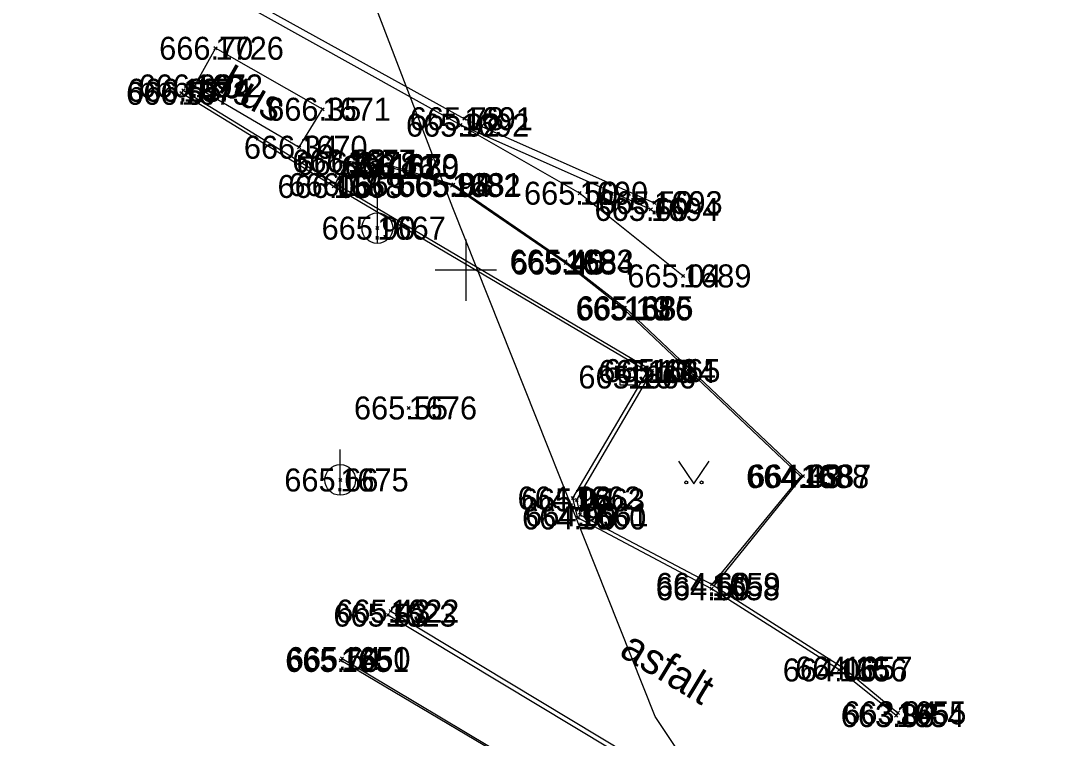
# Model space of a CAD drawing. Extents: x -844765 to -843273, y -997542 to -995529.
# Drawn here: x -844314.52 to -844280.68, y -996565.28 to -996541.86 of the extents above; entities that cross this region are included whole.
import ezdxf

# ---------------------------------------------------------------- set-up
doc = ezdxf.new("R2010")
doc.units = 0
for name, color, linetype in [('Betonový strop', 7, 'Continuous'), ('Dno', 7, 'Continuous'), ('Doplněk polohopisu', 7, 'Continuous'), ('Klenba', 7, 'Continuous'), ('Osa', 7, 'Continuous'), ('Rámeček', 7, 'Continuous'), ('Sítě podzemní nerozlišené', 7, 'Continuous'), ('Vrstva 1', 7, 'Continuous'), ('Výška', 7, 'Continuous'), ('Číslo bodu', 7, 'Continuous'), ('Řezy', 7, 'Continuous')]:
    doc.layers.add(name, color=color, linetype=linetype)

msp = doc.modelspace()

# ---------------------------------------------------------------- linework, layer by layer
at = {"layer": 'Betonový strop'}
for points in [[(-844313.39, -996537.68), (-844300.05, -996545.06), (-844293.86, -996547.8)], [(-844293.97, -996548.02), (-844300.17, -996545.27), (-844313.5, -996537.84)], [(-844309.22, -996544.13), (-844304.2, -996547.21), (-844293.93, -996553.28), (-844296.39, -996557.5), (-844296.28, -996557.99), (-844291.97, -996560.26), (-844287.67, -996562.99), (-844285.91, -996564.45)], [(-844285.97, -996564.54), (-844287.83, -996563.05), (-844291.99, -996560.4), (-844296.35, -996558.09), (-844296.51, -996557.44), (-844294.08, -996553.31), (-844304.31, -996547.27), (-844309.28, -996544.23)], [(-844300.17, -996545.27), (-844296.29, -996547.49), (-844292.92, -996550.19)], [(-844304.258, -996547.174), (-844303.86, -996546.44), (-844302.46, -996546.59), (-844300.41, -996547.21), (-844296.76, -996549.71), (-844294.81, -996551.23), (-844289.01, -996556.72), (-844291.908, -996560.299)], [(-844291.97, -996560.26), (-844289.08, -996556.74), (-844294.85, -996551.27), (-844296.75, -996549.77), (-844300.45, -996547.24), (-844302.46, -996546.65), (-844303.81, -996546.52), (-844304.2, -996547.21)], [(-844238.18, -996642.06), (-844239.24, -996647.29), (-844254.7, -996625.45), (-844265.09, -996610.79), (-844283.9, -996584.15), (-844283.04, -996578.62), (-844283.2, -996577.99), (-844284.98, -996575.45), (-844287.68, -996571.69), (-844290, -996569.21), (-844292.82, -996567.12), (-844302.54, -996561.26)], [(-844302.45, -996561.13), (-844292.72, -996567), (-844289.92, -996569.1), (-844287.58, -996571.6), (-844284.86, -996575.36), (-844283.13, -996577.92), (-844282.91, -996578.65), (-844283.74, -996584.11), (-844264.98, -996610.71), (-844254.61, -996625.37), (-844239.28, -996646.97), (-844238.31, -996642.04)], [(-844299.09, -996568.02), (-844298.56, -996566.02), (-844304.08, -996562.74)], [(-844304.04, -996562.68), (-844298.4, -996566.05), (-844298.99, -996568.07)]]:
    msp.add_lwpolyline(points, dxfattribs=at)
at = {"layer": 'Dno'}
msp.add_lwpolyline([(-844293.066, -996556.231), (-844292.566, -996556.981), (-844292.066, -996556.231)], dxfattribs=at)
for centre in [(-844292.816, -996556.931), (-844292.316, -996556.931)]:
    msp.add_circle(centre, 0.05, dxfattribs=at)
at = {"layer": 'Doplněk polohopisu'}
for p, q in [((-844302.89, -996549.13), (-844302.89, -996547.63)), ((-844294.98, -996553.49), (-844294.48, -996553.49)), ((-844304.1, -996557.35), (-844304.1, -996555.85))]:
    msp.add_line(p, q, dxfattribs=at)
msp.add_lwpolyline([(-844294.98, -996553.74), (-844294.48, -996553.74), (-844294.48, -996553.24), (-844294.98, -996553.24)], close=True, dxfattribs=at)
for centre in [(-844302.89, -996548.63), (-844304.1, -996556.85)]:
    msp.add_circle(centre, 0.5, dxfattribs=at)
at = {"layer": 'Klenba'}
for p, q in [((-844308.17, -996542.76), (-844308.85, -996543.99)), ((-844304.68, -996544.75), (-844308.17, -996542.76)), ((-844308.85, -996543.99), (-844305.44, -996545.99)), ((-844305.44, -996545.99), (-844304.68, -996544.75))]:
    msp.add_line(p, q, dxfattribs=at)
at = {"layer": 'Osa'}
msp.add_lwpolyline([(-844256.985, -996614.3), (-844264.955, -996604.805), (-844272.513, -996594.138), (-844280.435, -996583.425), (-844282.85, -996581.055), (-844288.34, -996572.812), (-844293.83, -996564.57), (-844300.425, -996547.97), (-844303.975, -996538.71), (-844307.525, -996529.45), (-844315.28, -996511.19), (-844322.67, -996492.595), (-844328.875, -996473.55)], dxfattribs=at)
at = {"layer": 'Rámeček'}
for p, q in [((-844300, -996549), (-844300, -996551)), ((-844299, -996550), (-844301, -996550))]:
    msp.add_line(p, q, dxfattribs=at)
at = {"layer": 'Sítě podzemní nerozlišené'}
for p, q in [((-844308.17, -996542.76), (-844308.22, -996542.71)), ((-844308.17, -996542.76), (-844308.22, -996542.81)), ((-844308.17, -996542.76), (-844308.12, -996542.71)), ((-844308.17, -996542.76), (-844308.12, -996542.81)), ((-844309.22, -996544.13), (-844309.27, -996544.08)), ((-844309.22, -996544.13), (-844309.27, -996544.18)), ((-844309.22, -996544.13), (-844309.17, -996544.08)), ((-844309.22, -996544.13), (-844309.17, -996544.18)), ((-844308.85, -996543.99), (-844308.9, -996543.94)), ((-844308.85, -996543.99), (-844308.9, -996544.04)), ((-844308.85, -996543.99), (-844308.8, -996543.94)), ((-844308.85, -996543.99), (-844308.8, -996544.04)), ((-844309.28, -996544.23), (-844309.33, -996544.18)), ((-844309.28, -996544.23), (-844309.33, -996544.28)), ((-844309.28, -996544.23), (-844309.23, -996544.18)), ((-844309.28, -996544.23), (-844309.23, -996544.28)), ((-844304.68, -996544.75), (-844304.73, -996544.7)), ((-844304.68, -996544.75), (-844304.73, -996544.8)), ((-844304.68, -996544.75), (-844304.63, -996544.7)), ((-844304.68, -996544.75), (-844304.63, -996544.8)), ((-844300.05, -996545.06), (-844300.1, -996545.01)), ((-844300.05, -996545.06), (-844300.1, -996545.11)), ((-844300.05, -996545.06), (-844300, -996545.01)), ((-844300.05, -996545.06), (-844300, -996545.11)), ((-844300.17, -996545.27), (-844300.22, -996545.22)), ((-844300.17, -996545.27), (-844300.22, -996545.32)), ((-844300.17, -996545.27), (-844300.12, -996545.22)), ((-844300.17, -996545.27), (-844300.12, -996545.32)), ((-844305.44, -996545.99), (-844305.49, -996545.94)), ((-844305.44, -996545.99), (-844305.49, -996546.04)), ((-844305.44, -996545.99), (-844305.39, -996545.94)), ((-844305.44, -996545.99), (-844305.39, -996546.04)), ((-844303.86, -996546.44), (-844303.91, -996546.39)), ((-844303.86, -996546.44), (-844303.91, -996546.49)), ((-844303.86, -996546.44), (-844303.81, -996546.39)), ((-844303.86, -996546.44), (-844303.81, -996546.49)), ((-844303.81, -996546.52), (-844303.86, -996546.47)), ((-844303.81, -996546.52), (-844303.76, -996546.47)), ((-844303.81, -996546.52), (-844303.86, -996546.57)), ((-844303.81, -996546.52), (-844303.76, -996546.57)), ((-844302.46, -996546.59), (-844302.51, -996546.54)), ((-844302.46, -996546.59), (-844302.51, -996546.64)), ((-844302.46, -996546.65), (-844302.51, -996546.6)), ((-844302.46, -996546.65), (-844302.51, -996546.7)), ((-844302.46, -996546.59), (-844302.41, -996546.54)), ((-844302.46, -996546.59), (-844302.41, -996546.64)), ((-844302.46, -996546.65), (-844302.41, -996546.6)), ((-844302.46, -996546.65), (-844302.41, -996546.7)), ((-844304.2, -996547.21), (-844304.25, -996547.16)), ((-844304.2, -996547.21), (-844304.15, -996547.16)), ((-844300.41, -996547.21), (-844300.46, -996547.16)), ((-844300.41, -996547.21), (-844300.36, -996547.16)), ((-844304.31, -996547.27), (-844304.36, -996547.22)), ((-844304.31, -996547.27), (-844304.36, -996547.32)), ((-844304.31, -996547.27), (-844304.26, -996547.22)), ((-844304.31, -996547.27), (-844304.26, -996547.32)), ((-844304.2, -996547.21), (-844304.25, -996547.26)), ((-844304.2, -996547.21), (-844304.15, -996547.26)), ((-844300.45, -996547.24), (-844300.5, -996547.19)), ((-844300.45, -996547.24), (-844300.5, -996547.29)), ((-844300.41, -996547.21), (-844300.46, -996547.26)), ((-844300.45, -996547.24), (-844300.4, -996547.19)), ((-844300.45, -996547.24), (-844300.4, -996547.29)), ((-844300.41, -996547.21), (-844300.36, -996547.26)), ((-844296.29, -996547.49), (-844296.34, -996547.44)), ((-844296.29, -996547.49), (-844296.34, -996547.54)), ((-844296.29, -996547.49), (-844296.24, -996547.44)), ((-844296.29, -996547.49), (-844296.24, -996547.54)), ((-844293.86, -996547.8), (-844293.91, -996547.75)), ((-844293.86, -996547.8), (-844293.91, -996547.85)), ((-844293.86, -996547.8), (-844293.81, -996547.75)), ((-844293.86, -996547.8), (-844293.81, -996547.85)), ((-844293.97, -996548.02), (-844294.02, -996547.97)), ((-844293.97, -996548.02), (-844294.02, -996548.07)), ((-844293.97, -996548.02), (-844293.92, -996547.97)), ((-844293.97, -996548.02), (-844293.92, -996548.07)), ((-844302.89, -996548.63), (-844302.94, -996548.58)), ((-844302.89, -996548.63), (-844302.94, -996548.68)), ((-844302.89, -996548.63), (-844302.84, -996548.58)), ((-844302.89, -996548.63), (-844302.84, -996548.68)), ((-844296.76, -996549.71), (-844296.81, -996549.66)), ((-844296.76, -996549.71), (-844296.81, -996549.76)), ((-844296.75, -996549.77), (-844296.8, -996549.72)), ((-844296.75, -996549.77), (-844296.8, -996549.82)), ((-844296.76, -996549.71), (-844296.71, -996549.66)), ((-844296.76, -996549.71), (-844296.71, -996549.76)), ((-844296.75, -996549.77), (-844296.7, -996549.72)), ((-844296.75, -996549.77), (-844296.7, -996549.82)), ((-844292.92, -996550.19), (-844292.97, -996550.14)), ((-844292.92, -996550.19), (-844292.97, -996550.24)), ((-844292.92, -996550.19), (-844292.87, -996550.14)), ((-844292.92, -996550.19), (-844292.87, -996550.24)), ((-844294.85, -996551.27), (-844294.9, -996551.22)), ((-844294.81, -996551.23), (-844294.86, -996551.18)), ((-844294.81, -996551.23), (-844294.86, -996551.28)), ((-844294.85, -996551.27), (-844294.8, -996551.22)), ((-844294.81, -996551.23), (-844294.76, -996551.18)), ((-844294.81, -996551.23), (-844294.76, -996551.28)), ((-844294.85, -996551.27), (-844294.9, -996551.32)), ((-844294.85, -996551.27), (-844294.8, -996551.32)), ((-844294.08, -996553.31), (-844294.13, -996553.26)), ((-844294.08, -996553.31), (-844294.03, -996553.26)), ((-844293.93, -996553.28), (-844293.98, -996553.23)), ((-844293.93, -996553.28), (-844293.88, -996553.23)), ((-844294.73, -996553.49), (-844294.78, -996553.44)), ((-844294.73, -996553.49), (-844294.78, -996553.54)), ((-844294.73, -996553.49), (-844294.68, -996553.44)), ((-844294.73, -996553.49), (-844294.68, -996553.54)), ((-844294.08, -996553.31), (-844294.13, -996553.36)), ((-844294.08, -996553.31), (-844294.03, -996553.36)), ((-844293.93, -996553.28), (-844293.98, -996553.33)), ((-844293.93, -996553.28), (-844293.88, -996553.33)), ((-844301.87, -996554.5), (-844301.92, -996554.45)), ((-844301.87, -996554.5), (-844301.92, -996554.55)), ((-844301.87, -996554.5), (-844301.82, -996554.45)), ((-844301.87, -996554.5), (-844301.82, -996554.55)), ((-844304.1, -996556.85), (-844304.15, -996556.8)), ((-844304.1, -996556.85), (-844304.15, -996556.9)), ((-844304.1, -996556.85), (-844304.05, -996556.8)), ((-844304.1, -996556.85), (-844304.05, -996556.9)), ((-844289.08, -996556.74), (-844289.13, -996556.69)), ((-844289.08, -996556.74), (-844289.13, -996556.79)), ((-844289.08, -996556.74), (-844289.03, -996556.69)), ((-844289.08, -996556.74), (-844289.03, -996556.79)), ((-844289.01, -996556.72), (-844289.06, -996556.67)), ((-844289.01, -996556.72), (-844289.06, -996556.77)), ((-844289.01, -996556.72), (-844288.96, -996556.67)), ((-844289.01, -996556.72), (-844288.96, -996556.77)), ((-844296.51, -996557.44), (-844296.56, -996557.39)), ((-844296.51, -996557.44), (-844296.56, -996557.49)), ((-844296.51, -996557.44), (-844296.46, -996557.39)), ((-844296.51, -996557.44), (-844296.46, -996557.49)), ((-844296.39, -996557.5), (-844296.44, -996557.45)), ((-844296.39, -996557.5), (-844296.44, -996557.55)), ((-844296.39, -996557.5), (-844296.34, -996557.45)), ((-844296.39, -996557.5), (-844296.34, -996557.55)), ((-844296.28, -996557.99), (-844296.33, -996557.94)), ((-844296.28, -996557.99), (-844296.33, -996558.04)), ((-844296.28, -996557.99), (-844296.23, -996557.94)), ((-844296.28, -996557.99), (-844296.23, -996558.04)), ((-844296.35, -996558.09), (-844296.4, -996558.04)), ((-844296.35, -996558.09), (-844296.4, -996558.14)), ((-844296.35, -996558.09), (-844296.3, -996558.04)), ((-844296.35, -996558.09), (-844296.3, -996558.14)), ((-844291.99, -996560.4), (-844292.04, -996560.35)), ((-844291.97, -996560.26), (-844292.02, -996560.21)), ((-844291.97, -996560.26), (-844292.02, -996560.31)), ((-844291.99, -996560.4), (-844291.94, -996560.35)), ((-844291.97, -996560.26), (-844291.92, -996560.21)), ((-844291.97, -996560.26), (-844291.92, -996560.31)), ((-844291.99, -996560.4), (-844292.04, -996560.45)), ((-844291.99, -996560.4), (-844291.94, -996560.45)), ((-844302.54, -996561.26), (-844302.59, -996561.21)), ((-844302.54, -996561.26), (-844302.59, -996561.31)), ((-844302.54, -996561.26), (-844302.49, -996561.21)), ((-844302.54, -996561.26), (-844302.49, -996561.31)), ((-844302.45, -996561.13), (-844302.5, -996561.08)), ((-844302.45, -996561.13), (-844302.5, -996561.18)), ((-844302.45, -996561.13), (-844302.4, -996561.08)), ((-844302.45, -996561.13), (-844302.4, -996561.18)), ((-844304.08, -996562.74), (-844304.13, -996562.69)), ((-844304.08, -996562.74), (-844304.13, -996562.79)), ((-844304.04, -996562.68), (-844304.09, -996562.63)), ((-844304.04, -996562.68), (-844304.09, -996562.73)), ((-844304.08, -996562.74), (-844304.03, -996562.69)), ((-844304.08, -996562.74), (-844304.03, -996562.79)), ((-844304.04, -996562.68), (-844303.99, -996562.63)), ((-844304.04, -996562.68), (-844303.99, -996562.73)), ((-844287.83, -996563.05), (-844287.88, -996563)), ((-844287.83, -996563.05), (-844287.88, -996563.1)), ((-844287.83, -996563.05), (-844287.78, -996563)), ((-844287.83, -996563.05), (-844287.78, -996563.1)), ((-844287.67, -996562.99), (-844287.72, -996562.94)), ((-844287.67, -996562.99), (-844287.72, -996563.04)), ((-844287.67, -996562.99), (-844287.62, -996562.94)), ((-844287.67, -996562.99), (-844287.62, -996563.04)), ((-844285.91, -996564.45), (-844285.96, -996564.4)), ((-844285.91, -996564.45), (-844285.86, -996564.4)), ((-844285.97, -996564.54), (-844286.02, -996564.49)), ((-844285.97, -996564.54), (-844286.02, -996564.59)), ((-844285.97, -996564.54), (-844285.92, -996564.49)), ((-844285.97, -996564.54), (-844285.92, -996564.59)), ((-844285.91, -996564.45), (-844285.96, -996564.5)), ((-844285.91, -996564.45), (-844285.86, -996564.5))]:
    msp.add_line(p, q, dxfattribs=at)

# ---------------------------------------------------------------- texts
at = {"layer": 'Vrstva 1'}
msp.add_text('bus', height=1, rotation=330.3082, dxfattribs=at).set_placement((-844308.116, -996544.152))
at = {"layer": 'Výška'}
msp.add_text('asfalt', height=1, rotation=328.8979, dxfattribs=at).set_placement((-844295.042, -996562.564))
at = {"layer": 'Číslo bodu'}
for s, p in [('1726', (-844308.17, -996543.135)), ('1674', (-844309.22, -996544.505)), ('1672', (-844308.85, -996544.365)), ('1673', (-844309.28, -996544.605)), ('1671', (-844304.68, -996545.125)), ('1691', (-844300.05, -996545.435)), ('1692', (-844300.17, -996545.645)), ('1670', (-844305.44, -996546.365)), ('1677', (-844303.86, -996546.815)), ('1678', (-844303.81, -996546.895)), ('1679', (-844302.46, -996546.965)), ('1680', (-844302.46, -996547.025)), ('1669', (-844304.2, -996547.585)), ('1681', (-844300.41, -996547.585)), ('1668', (-844304.31, -996547.645)), ('1682', (-844300.45, -996547.615)), ('1690', (-844296.29, -996547.865)), ('1693', (-844293.86, -996548.175)), ('1694', (-844293.97, -996548.395)), ('1667', (-844302.89, -996549.005)), ('1683', (-844296.76, -996550.085)), ('1684', (-844296.75, -996550.145)), ('1689', (-844292.92, -996550.565)), ('1686', (-844294.85, -996551.645)), ('1685', (-844294.81, -996551.605)), ('1664', (-844294.08, -996553.685)), ('1665', (-844293.93, -996553.655)), ('1666', (-844294.73, -996553.865)), ('1676', (-844301.87, -996554.875)), ('1675', (-844304.1, -996557.225)), ('1688', (-844289.08, -996557.115)), ('1687', (-844289.01, -996557.095)), ('1662', (-844296.51, -996557.815)), ('1663', (-844296.39, -996557.875)), ('1661', (-844296.28, -996558.365)), ('1660', (-844296.35, -996558.465)), ('1658', (-844291.99, -996560.775)), ('1659', (-844291.97, -996560.635)), ('1623', (-844302.54, -996561.635)), ('1622', (-844302.45, -996561.505)), ('1651', (-844304.08, -996563.115)), ('1650', (-844304.04, -996563.055)), ('1656', (-844287.83, -996563.425)), ('1657', (-844287.67, -996563.365)), ('1655', (-844285.91, -996564.825)), ('1654', (-844285.97, -996564.915))]:
    msp.add_text(s, height=0.75, dxfattribs=at).set_placement(p)
at = {"layer": 'Řezy'}
for s, p in [('666.70', (-844310.006, -996543.135)), ('666.65', (-844311.045, -996544.505)), ('666.69', (-844310.678, -996544.365)), ('666.57', (-844311.084, -996544.605)), ('666.35', (-844306.484, -996545.125)), ('665.78', (-844301.833, -996545.435)), ('665.92', (-844301.956, -996545.645)), ('666.34', (-844307.244, -996546.365)), ('666.22', (-844305.664, -996546.815)), ('666.31', (-844305.525, -996546.895)), ('666.16', (-844304.072, -996547.025)), ('666.11', (-844303.963, -996546.965)), ('666.18', (-844305.791, -996547.585)), ('665.88', (-844302.193, -996547.585)), ('666.05', (-844306.146, -996547.645)), ('665.94', (-844302.236, -996547.615)), ('665.50', (-844298.106, -996547.865)), ('665.50', (-844295.676, -996548.175)), ('665.60', (-844295.806, -996548.395)), ('665.90', (-844304.709, -996549.005)), ('665.40', (-844298.576, -996550.085)), ('665.45', (-844298.533, -996550.145)), ('665.04', (-844294.736, -996550.565)), ('665.19', (-844296.424, -996551.645)), ('665.13', (-844296.381, -996551.605)), ('665.10', (-844295.683, -996553.685)), ('665.19', (-844295.504, -996553.655)), ('665.10', (-844296.333, -996553.865)), ('665.55', (-844303.653, -996554.875)), ('665.66', (-844305.925, -996557.225)), ('664.43', (-844290.863, -996557.115)), ('664.39', (-844290.796, -996557.095)), ('664.96', (-844298.317, -996557.815)), ('665.04', (-844298.206, -996557.875)), ('664.99', (-844298.069, -996558.365)), ('664.90', (-844298.169, -996558.465)), ('664.60', (-844293.806, -996560.635)), ('664.50', (-844293.806, -996560.775)), ('665.53', (-844304.323, -996561.635)), ('665.43', (-844304.233, -996561.505)), ('665.70', (-844305.896, -996563.115)), ('665.64', (-844305.844, -996563.055)), ('664.06', (-844289.666, -996563.425)), ('664.16', (-844289.261, -996563.365)), ('663.94', (-844287.696, -996564.825)), ('663.86', (-844287.774, -996564.915))]:
    msp.add_text(s, height=0.75, dxfattribs=at).set_placement(p)

doc.saveas('drawing.dxf')
